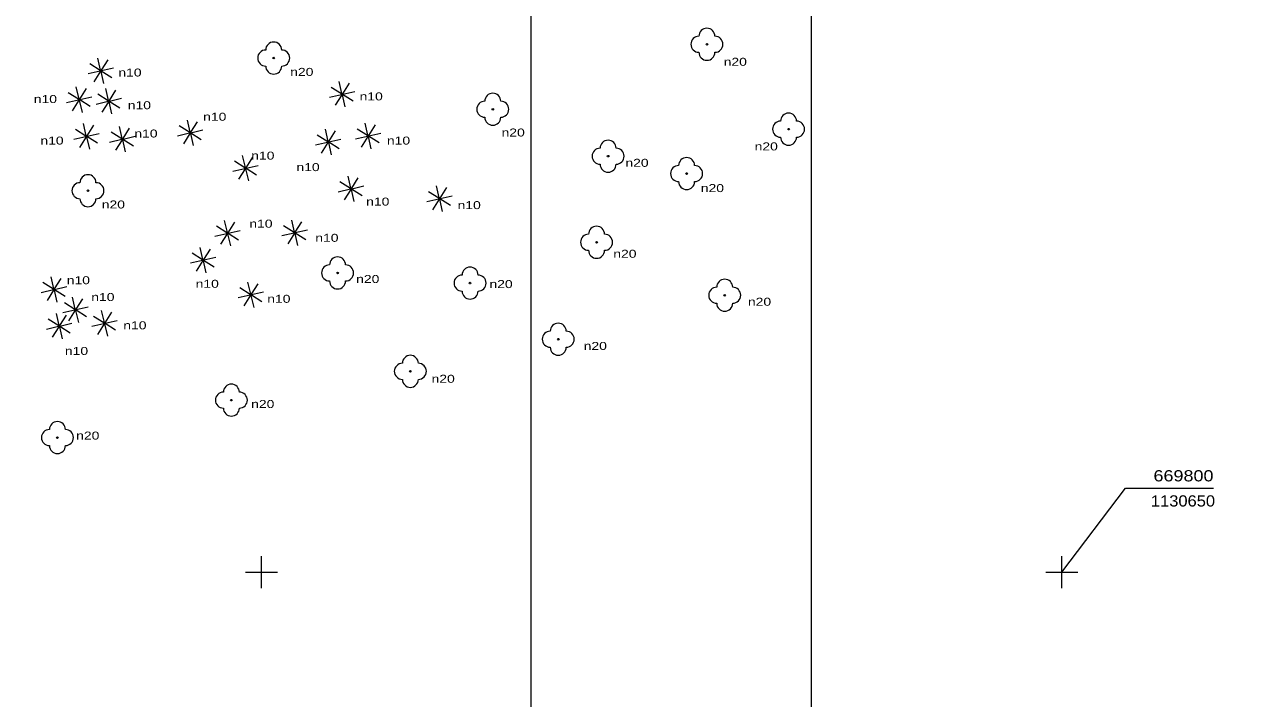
# Model space of a CAD drawing. Extents: x -670514 to -669423, y -1130798 to -1130123.
# Drawn here: x -669864.8 to -669788.7, y -1130657.9 to -1130615.8 of the extents above; entities that cross this region are included whole.
import ezdxf
from ezdxf.enums import TextEntityAlignment as Align

# ---------------------------------------------------------------- set-up
doc = ezdxf.new("R2010")
doc.units = 0
doc.header["$LTSCALE"] = 0.24
for name, color, linetype, lineweight in [('22', 7, 'Continuous', 13), ('60', 7, 'Continuous', 13), ('61', 7, 'Continuous', 13)]:
    doc.layers.add(name, color=color, linetype=linetype, lineweight=lineweight)
doc.layers.add('47', color=7, linetype='Continuous')

msp = doc.modelspace()

# ---------------------------------------------------------------- linework, layer by layer
at = {"layer": '22'}
for p, q in [((-669860.049, -1130618.649), (-669860.221, -1130617.895)), ((-669860.075, -1130618.669), (-669860.731, -1130618.255)), ((-669859.607, -1130617.999), (-669860.021, -1130618.655)), ((-669860.001, -1130618.681), (-669859.247, -1130618.509)), ((-669860.835, -1130618.869), (-669860.081, -1130618.697)), ((-669860.061, -1130618.723), (-669860.475, -1130619.379)), ((-669860.033, -1130618.729), (-669859.861, -1130619.483)), ((-669859.351, -1130619.123), (-669860.007, -1130618.709)), ((-669844.972, -1130620.118), (-669845.144, -1130619.364)), ((-669861.425, -1130620.473), (-669862.081, -1130620.059)), ((-669861.399, -1130620.453), (-669861.571, -1130619.699)), ((-669860.957, -1130619.803), (-669861.371, -1130620.459)), ((-669859.577, -1130620.566), (-669860.233, -1130620.152)), ((-669859.551, -1130620.546), (-669859.723, -1130619.792)), ((-669859.109, -1130619.896), (-669859.523, -1130620.552)), ((-669845.758, -1130620.338), (-669845.004, -1130620.166)), ((-669844.998, -1130620.138), (-669845.654, -1130619.724)), ((-669844.984, -1130620.192), (-669845.398, -1130620.848)), ((-669844.956, -1130620.198), (-669844.784, -1130620.952)), ((-669844.53, -1130619.468), (-669844.944, -1130620.124)), ((-669844.274, -1130620.592), (-669844.93, -1130620.178)), ((-669844.924, -1130620.15), (-669844.17, -1130619.978)), ((-669862.185, -1130620.673), (-669861.431, -1130620.501)), ((-669861.411, -1130620.527), (-669861.825, -1130621.183)), ((-669861.383, -1130620.533), (-669861.211, -1130621.287)), ((-669860.701, -1130620.927), (-669861.357, -1130620.513)), ((-669861.351, -1130620.485), (-669860.597, -1130620.313)), ((-669860.337, -1130620.766), (-669859.583, -1130620.594)), ((-669859.563, -1130620.62), (-669859.977, -1130621.276)), ((-669859.535, -1130620.626), (-669859.363, -1130621.38)), ((-669858.853, -1130621.02), (-669859.509, -1130620.606)), ((-669859.503, -1130620.578), (-669858.749, -1130620.406)), ((-669860.968, -1130622.764), (-669861.624, -1130622.35)), ((-669860.942, -1130622.744), (-669861.114, -1130621.99)), ((-669860.5, -1130622.094), (-669860.914, -1130622.75)), ((-669858.698, -1130622.923), (-669858.87, -1130622.169)), ((-669858.256, -1130622.273), (-669858.67, -1130622.929)), ((-669854.481, -1130622.546), (-669855.137, -1130622.132)), ((-669854.455, -1130622.526), (-669854.627, -1130621.772)), ((-669854.013, -1130621.876), (-669854.427, -1130622.532)), ((-669854.407, -1130622.558), (-669853.653, -1130622.386)), ((-669845.834, -1130623.099), (-669846.006, -1130622.345)), ((-669845.392, -1130622.449), (-669845.806, -1130623.105)), ((-669843.372, -1130622.742), (-669844.028, -1130622.328)), ((-669843.346, -1130622.722), (-669843.518, -1130621.968)), ((-669842.904, -1130622.072), (-669843.318, -1130622.728)), ((-669861.728, -1130622.964), (-669860.974, -1130622.792)), ((-669860.954, -1130622.818), (-669861.368, -1130623.474)), ((-669860.926, -1130622.824), (-669860.754, -1130623.578)), ((-669860.244, -1130623.218), (-669860.9, -1130622.804)), ((-669860.894, -1130622.776), (-669860.14, -1130622.604)), ((-669859.484, -1130623.143), (-669858.73, -1130622.971)), ((-669858.724, -1130622.943), (-669859.38, -1130622.529)), ((-669858.71, -1130622.997), (-669859.124, -1130623.653)), ((-669858.682, -1130623.003), (-669858.51, -1130623.757)), ((-669858, -1130623.397), (-669858.656, -1130622.983)), ((-669858.65, -1130622.955), (-669857.896, -1130622.783)), ((-669855.241, -1130622.746), (-669854.487, -1130622.574)), ((-669854.467, -1130622.6), (-669854.881, -1130623.256)), ((-669854.439, -1130622.606), (-669854.267, -1130623.36)), ((-669853.757, -1130623), (-669854.413, -1130622.586)), ((-669846.62, -1130623.319), (-669845.866, -1130623.147)), ((-669845.86, -1130623.119), (-669846.516, -1130622.705)), ((-669845.846, -1130623.173), (-669846.26, -1130623.829)), ((-669845.818, -1130623.179), (-669845.646, -1130623.933)), ((-669845.136, -1130623.573), (-669845.792, -1130623.159)), ((-669845.786, -1130623.131), (-669845.032, -1130622.959)), ((-669844.132, -1130622.942), (-669843.378, -1130622.77)), ((-669843.358, -1130622.796), (-669843.772, -1130623.452)), ((-669843.33, -1130622.802), (-669843.158, -1130623.556)), ((-669842.648, -1130623.196), (-669843.304, -1130622.782)), ((-669843.298, -1130622.754), (-669842.544, -1130622.582)), ((-669851.005, -1130624.738), (-669851.177, -1130623.984)), ((-669851.031, -1130624.758), (-669851.687, -1130624.344)), ((-669850.563, -1130624.088), (-669850.977, -1130624.744)), ((-669850.957, -1130624.77), (-669850.203, -1130624.598)), ((-669851.791, -1130624.958), (-669851.037, -1130624.786)), ((-669851.017, -1130624.812), (-669851.431, -1130625.468)), ((-669850.989, -1130624.818), (-669850.817, -1130625.572)), ((-669850.307, -1130625.212), (-669850.963, -1130624.798)), ((-669844.412, -1130626.022), (-669844.584, -1130625.268)), ((-669843.97, -1130625.372), (-669844.384, -1130626.028)), ((-669845.198, -1130626.242), (-669844.444, -1130626.07)), ((-669844.438, -1130626.042), (-669845.094, -1130625.628)), ((-669844.424, -1130626.096), (-669844.838, -1130626.752)), ((-669844.396, -1130626.102), (-669844.224, -1130626.856)), ((-669843.714, -1130626.496), (-669844.37, -1130626.082)), ((-669844.364, -1130626.054), (-669843.61, -1130625.882)), ((-669838.918, -1130626.656), (-669839.574, -1130626.242)), ((-669838.892, -1130626.636), (-669839.064, -1130625.882)), ((-669838.45, -1130625.986), (-669838.864, -1130626.642)), ((-669839.678, -1130626.856), (-669838.924, -1130626.684)), ((-669838.904, -1130626.71), (-669839.318, -1130627.366)), ((-669838.876, -1130626.716), (-669838.704, -1130627.47)), ((-669838.194, -1130627.11), (-669838.85, -1130626.696)), ((-669838.844, -1130626.668), (-669838.09, -1130626.496)), ((-669852.158, -1130628.816), (-669852.814, -1130628.402)), ((-669852.132, -1130628.796), (-669852.304, -1130628.042)), ((-669851.69, -1130628.146), (-669852.104, -1130628.802)), ((-669847.96, -1130628.787), (-669848.616, -1130628.373)), ((-669847.934, -1130628.767), (-669848.106, -1130628.013)), ((-669847.492, -1130628.117), (-669847.906, -1130628.773)), ((-669852.918, -1130629.016), (-669852.164, -1130628.844)), ((-669852.144, -1130628.87), (-669852.558, -1130629.526)), ((-669852.116, -1130628.876), (-669851.944, -1130629.63)), ((-669851.434, -1130629.27), (-669852.09, -1130628.856)), ((-669852.084, -1130628.828), (-669851.33, -1130628.656)), ((-669848.72, -1130628.987), (-669847.966, -1130628.815)), ((-669847.946, -1130628.841), (-669848.36, -1130629.497)), ((-669847.918, -1130628.847), (-669847.746, -1130629.601)), ((-669847.236, -1130629.241), (-669847.892, -1130628.827)), ((-669847.886, -1130628.799), (-669847.132, -1130628.627)), ((-669853.681, -1130630.495), (-669854.337, -1130630.081)), ((-669853.655, -1130630.475), (-669853.827, -1130629.721)), ((-669853.213, -1130629.825), (-669853.627, -1130630.481)), ((-669854.441, -1130630.695), (-669853.687, -1130630.523)), ((-669853.667, -1130630.549), (-669854.081, -1130631.205)), ((-669853.639, -1130630.555), (-669853.467, -1130631.309)), ((-669852.957, -1130630.949), (-669853.613, -1130630.535)), ((-669853.607, -1130630.507), (-669852.853, -1130630.335)), ((-669862.971, -1130632.314), (-669863.143, -1130631.56)), ((-669863.757, -1130632.534), (-669863.003, -1130632.362)), ((-669862.997, -1130632.334), (-669863.653, -1130631.92)), ((-669862.529, -1130631.664), (-669862.943, -1130632.32)), ((-669862.273, -1130632.788), (-669862.929, -1130632.374)), ((-669862.923, -1130632.346), (-669862.169, -1130632.174)), ((-669850.696, -1130632.659), (-669851.352, -1130632.245)), ((-669850.67, -1130632.639), (-669850.842, -1130631.885)), ((-669850.228, -1130631.989), (-669850.642, -1130632.645)), ((-669862.983, -1130632.388), (-669863.397, -1130633.044)), ((-669862.955, -1130632.394), (-669862.783, -1130633.148)), ((-669861.629, -1130633.576), (-669861.801, -1130632.822)), ((-669861.187, -1130632.926), (-669861.601, -1130633.582)), ((-669851.456, -1130632.859), (-669850.702, -1130632.687)), ((-669850.682, -1130632.713), (-669851.096, -1130633.369)), ((-669850.654, -1130632.719), (-669850.482, -1130633.473)), ((-669849.972, -1130633.113), (-669850.628, -1130632.699)), ((-669850.622, -1130632.671), (-669849.868, -1130632.499)), ((-669862.642, -1130634.601), (-669862.814, -1130633.847)), ((-669862.415, -1130633.796), (-669861.661, -1130633.624)), ((-669861.655, -1130633.596), (-669862.311, -1130633.182)), ((-669861.641, -1130633.65), (-669862.055, -1130634.306)), ((-669861.613, -1130633.656), (-669861.441, -1130634.41)), ((-669860.931, -1130634.05), (-669861.587, -1130633.636)), ((-669861.581, -1130633.608), (-669860.827, -1130633.436)), ((-669859.817, -1130634.423), (-669859.989, -1130633.669)), ((-669859.375, -1130633.773), (-669859.789, -1130634.429)), ((-669863.428, -1130634.821), (-669862.674, -1130634.649)), ((-669862.668, -1130634.621), (-669863.324, -1130634.207)), ((-669862.2, -1130633.951), (-669862.614, -1130634.607)), ((-669861.944, -1130635.075), (-669862.6, -1130634.661)), ((-669862.594, -1130634.633), (-669861.84, -1130634.461)), ((-669860.603, -1130634.643), (-669859.849, -1130634.471)), ((-669859.843, -1130634.443), (-669860.499, -1130634.029)), ((-669859.829, -1130634.497), (-669860.243, -1130635.153)), ((-669859.801, -1130634.503), (-669859.629, -1130635.257)), ((-669859.119, -1130634.897), (-669859.775, -1130634.483)), ((-669859.769, -1130634.455), (-669859.015, -1130634.283)), ((-669862.654, -1130634.675), (-669863.068, -1130635.331)), ((-669862.626, -1130634.681), (-669862.454, -1130635.435))]:
    msp.add_line(p, q, dxfattribs=at)
for centre, radius in [((-669822.169, -1130617.036), 0.05), ((-669849.237, -1130617.894), 0.05), ((-669860.041, -1130618.689), 0.04), ((-669844.964, -1130620.158), 0.04), ((-669861.391, -1130620.493), 0.04), ((-669859.543, -1130620.586), 0.04), ((-669835.547, -1130621.095), 0.05), ((-669817.067, -1130622.337), 0.05), ((-669860.934, -1130622.784), 0.04), ((-669858.69, -1130622.963), 0.04), ((-669854.447, -1130622.566), 0.04), ((-669845.826, -1130623.139), 0.04), ((-669843.338, -1130622.762), 0.04), ((-669828.343, -1130624.025), 0.05), ((-669850.997, -1130624.778), 0.04), ((-669823.437, -1130625.11), 0.05), ((-669860.839, -1130626.179), 0.05), ((-669844.404, -1130626.062), 0.04), ((-669838.884, -1130626.676), 0.04), ((-669852.124, -1130628.836), 0.04), ((-669847.926, -1130628.807), 0.04), ((-669829.062, -1130629.403), 0.05), ((-669853.647, -1130630.515), 0.04), ((-669845.243, -1130631.319), 0.05), ((-669862.963, -1130632.354), 0.04), ((-669836.969, -1130631.952), 0.05), ((-669850.662, -1130632.679), 0.04), ((-669821.06, -1130632.71), 0.05), ((-669861.621, -1130633.616), 0.04), ((-669862.634, -1130634.641), 0.04), ((-669859.809, -1130634.463), 0.04), ((-669831.459, -1130635.457), 0.05), ((-669840.699, -1130637.463), 0.05), ((-669851.881, -1130639.263), 0.05), ((-669862.75, -1130641.601), 0.05)]:
    msp.add_circle(centre, radius, dxfattribs=at)
for centre, start, end in [((-669822.169, -1130616.536), 0, 180), ((-669849.237, -1130617.394), 0, 180), ((-669822.669, -1130617.036), 90, 270), ((-669821.669, -1130617.036), 270, 90), ((-669849.737, -1130617.894), 90, 270), ((-669848.737, -1130617.894), 270, 90), ((-669822.169, -1130617.536), 180, 0), ((-669849.237, -1130618.394), 180, 0), ((-669835.547, -1130620.595), 0, 180), ((-669836.047, -1130621.095), 90, 270), ((-669835.047, -1130621.095), 270, 90), ((-669835.547, -1130621.595), 180, 0), ((-669817.067, -1130621.837), 0, 180), ((-669817.567, -1130622.337), 90, 270), ((-669816.567, -1130622.337), 270, 90), ((-669828.343, -1130623.525), 0, 180), ((-669817.067, -1130622.837), 180, 0), ((-669828.843, -1130624.025), 90, 270), ((-669827.843, -1130624.025), 270, 90), ((-669828.343, -1130624.525), 180, 0), ((-669823.937, -1130625.11), 90, 270), ((-669823.437, -1130624.61), 0, 180), ((-669822.937, -1130625.11), 270, 90), ((-669860.839, -1130625.679), 0, 180), ((-669861.339, -1130626.179), 90, 270), ((-669860.339, -1130626.179), 270, 90), ((-669823.437, -1130625.61), 180, 0), ((-669860.839, -1130626.679), 180, 0), ((-669829.062, -1130628.903), 0, 180), ((-669829.562, -1130629.403), 90, 270), ((-669828.562, -1130629.403), 270, 90), ((-669829.062, -1130629.903), 180, 0), ((-669845.743, -1130631.319), 90, 270), ((-669845.243, -1130630.819), 0, 180), ((-669844.743, -1130631.319), 270, 90), ((-669837.469, -1130631.952), 90, 270), ((-669836.969, -1130631.452), 0, 180), ((-669836.469, -1130631.952), 270, 90), ((-669845.243, -1130631.819), 180, 0), ((-669821.56, -1130632.71), 90, 270), ((-669821.06, -1130632.21), 0, 180), ((-669820.56, -1130632.71), 270, 90), ((-669836.969, -1130632.452), 180, 0), ((-669821.06, -1130633.21), 180, 0), ((-669831.459, -1130634.957), 0, 180), ((-669831.959, -1130635.457), 90, 270), ((-669830.959, -1130635.457), 270, 90), ((-669831.459, -1130635.957), 180, 0), ((-669840.699, -1130636.963), 0, 180), ((-669841.199, -1130637.463), 90, 270), ((-669840.199, -1130637.463), 270, 90), ((-669851.881, -1130638.763), 0, 180), ((-669840.699, -1130637.963), 180, 0), ((-669852.381, -1130639.263), 90, 270), ((-669851.381, -1130639.263), 270, 90), ((-669851.881, -1130639.763), 180, 0), ((-669862.75, -1130641.101), 0, 180), ((-669863.25, -1130641.601), 90, 270), ((-669862.25, -1130641.601), 270, 90), ((-669862.75, -1130642.101), 180, 0)]:
    msp.add_arc(centre, 0.5, start, end, dxfattribs=at)
at = {"layer": '60'}
for points in [[(-669833.172, -1130763.536), (-669423.172, -1130763.536), (-669423.172, -1130476.536), (-669833.172, -1130476.536)], [(-670225.642, -1130798.198), (-669815.642, -1130798.198), (-669815.642, -1130511.198), (-670225.642, -1130511.198)]]:
    msp.add_lwpolyline(points, close=True, dxfattribs=at)
at = {"layer": '61'}
for p, q in [((-669850, -1130651), (-669850, -1130649)), ((-669800, -1130651), (-669800, -1130649)), ((-669851, -1130650), (-669849, -1130650)), ((-669801, -1130650), (-669799, -1130650))]:
    msp.add_line(p, q, dxfattribs=at)
msp.add_lwpolyline([(-669800, -1130650), (-669796.023, -1130644.762), (-669790.523, -1130644.762)], dxfattribs=at)

# ---------------------------------------------------------------- texts
at = {"layer": '47', "width": 1.3}
for s, p in [('n20', (-669820.3975, -1130618.379)), ('n10', (-669858.2155, -1130619.049)), ('n20', (-669847.4795, -1130619.01)), ('n10', (-669863.4995, -1130620.705)), ('n10', (-669843.1455, -1130620.54)), ('n10', (-669857.6275, -1130621.092)), ('n10', (-669852.9175, -1130621.81)), ('n10', (-669857.2155, -1130622.859)), ('n20', (-669834.2745, -1130622.796)), ('n10', (-669863.0875, -1130623.3)), ('n10', (-669841.4385, -1130623.3)), ('n20', (-669818.4635, -1130623.664)), ('n10', (-669849.9155, -1130624.239)), ('n10', (-669847.0895, -1130624.957)), ('n20', (-669826.5375, -1130624.689)), ('n20', (-669821.8275, -1130626.267)), ('n20', (-669859.2535, -1130627.292)), ('n10', (-669842.7335, -1130627.11)), ('n10', (-669837.0235, -1130627.331)), ('n10', (-669850.0335, -1130628.49)), ('n10', (-669845.9125, -1130629.373)), ('n20', (-669827.2945, -1130630.369)), ('n10', (-669861.4395, -1130632.023)), ('n20', (-669843.3585, -1130631.946)), ('n10', (-669853.3885, -1130632.244)), ('n20', (-669835.0315, -1130632.262)), ('n10', (-669859.9085, -1130633.072)), ('n10', (-669848.9145, -1130633.183)), ('n20', (-669818.8835, -1130633.366)), ('n10', (-669857.9075, -1130634.839)), ('n10', (-669861.5565, -1130636.44)), ('n20', (-669829.1445, -1130636.127)), ('n20', (-669838.6485, -1130638.178)), ('n20', (-669849.9185, -1130639.755)), ('n20', (-669860.8515, -1130641.727))]:
    msp.add_text(s, height=0.5, dxfattribs=at).set_placement(p, align=Align.CENTER)
at = {"layer": '61'}
for s, width, p in [('669800', 1.2, (-669792.396, -1130644.337)), ('1130650', 1.1, (-669792.4275, -1130645.907))]:
    msp.add_text(s, height=0.7, dxfattribs=dict(at, width=width)).set_placement(p, align=Align.CENTER)

doc.saveas('drawing.dxf')
